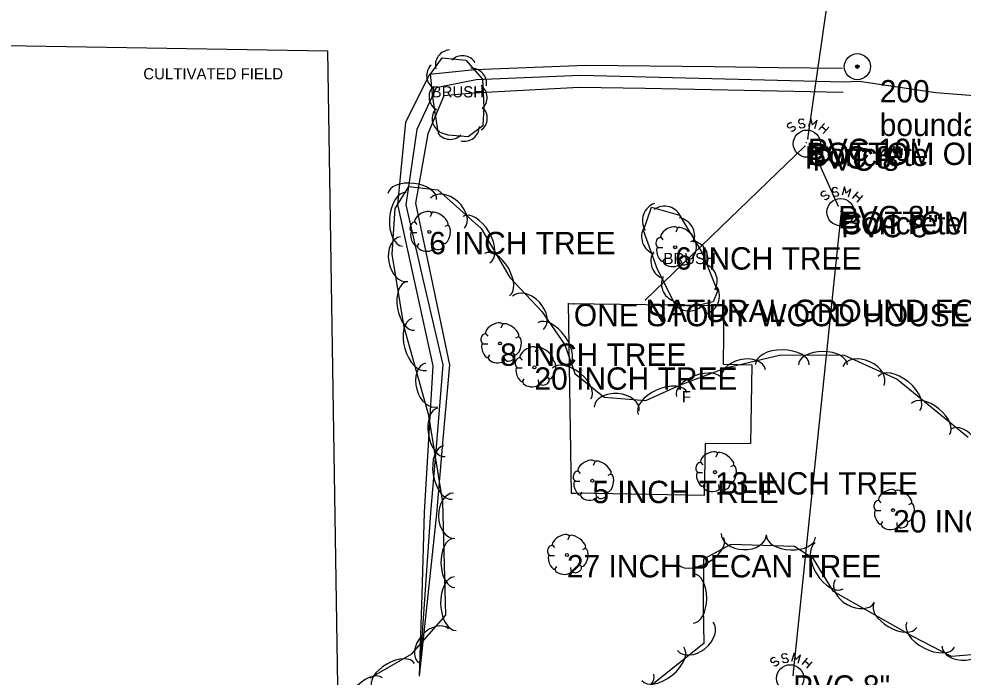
# Model space of a CAD drawing. Extents: x 1802180 to 1804859, y 572524 to 575172.
# Drawn here: x 1803144.4 to 1803355.3, y 573590.8 to 573738 of the extents above; entities that cross this region are included whole.
import ezdxf

# ---------------------------------------------------------------- set-up
doc = ezdxf.new("R2010")
doc.units = 0
for name, color, linetype in [('S_BUILDING', 7, 'Continuous'), ('S_BUILDING_ANNOT', 7, 'Continuous'), ('S_DITCHLINE', 7, 'Continuous'), ('S_IRON_PIN', 7, 'Continuous'), ('S_IRON_PIN_ANNOT', 7, 'Continuous'), ('S_MANHOLE_ANNOT', 7, 'Continuous'), ('S_MISC_BOUNDARY', 7, 'Continuous'), ('S_MISC_BOUNDARY_ANNOT', 7, 'Continuous'), ('S_MSC_PT_SYM', 7, 'Continuous'), ('S_SANITARY_SEWER', 7, 'Continuous'), ('S_SANITARY_SEWER_ANNOT', 7, 'Continuous'), ('S_SURVEY_TEXT_ANNOT', 7, 'Continuous'), ('S_TREE', 7, 'Continuous'), ('S_TREE_ANNOT', 7, 'Continuous'), ('S_UTL_PT_SYM', 7, 'Continuous')]:
    doc.layers.add(name, color=color, linetype=linetype)

msp = doc.modelspace()

# ---------------------------------------------------------------- linework, layer by layer
at = {"layer": 'S_BUILDING'}
for points in [[(1803267.07, 573674.42), (1803267.76, 573631.93), (1803268.74, 573631.95)], [(1803267.07, 573674.36), (1803301.86, 573673.93), (1803301.66, 573660.77), (1803308.1, 573660.63), (1803307.82, 573643.02), (1803297.64, 573642.97), (1803297.43, 573631.4), (1803268.85, 573631.96)]]:
    msp.add_lwpolyline(points, dxfattribs=at)
at = {"layer": 'S_DITCHLINE'}
for points in [[(1803328.37, 573726.88), (1803314.02, 573727.05), (1803299.67, 573727.21), (1803285.33, 573727.38), (1803270.98, 573727.54), (1803246.23, 573726.54), (1803236.12, 573725.56), (1803230.72, 573714.87), (1803228.93, 573696.45), (1803232.87, 573678.43), (1803236.81, 573660.4), (1803235.86, 573644.01), (1803234.91, 573627.61), (1803234.34, 573609.32), (1803233.78, 573591.03)], [(1803395.56, 573715.37), (1803382.79, 573717.59), (1803370.01, 573719.81), (1803349.16, 573721.42), (1803332.09, 573723.99), (1803328.45, 573723.83), (1803313.8, 573724.2), (1803299.14, 573724.57), (1803284.49, 573724.93), (1803269.83, 573725.3), (1803246.52, 573724.3), (1803237.61, 573722.54), (1803233.26, 573713.21), (1803230.79, 573696.36), (1803234.92, 573678.51), (1803239.04, 573660.67), (1803237.69, 573644.13), (1803236.34, 573627.59), (1803235.06, 573609.31), (1803233.78, 573591.03)], [(1803328.46, 573721.52), (1803313.73, 573721.81), (1803299, 573722.09), (1803284.28, 573722.37), (1803269.55, 573722.65), (1803245.87, 573721.33), (1803239.32, 573720.76), (1803235.74, 573712.29), (1803232.93, 573696.77), (1803236.73, 573678.71), (1803240.52, 573660.66), (1803239.1, 573643.99), (1803237.68, 573627.32), (1803235.73, 573609.17), (1803233.78, 573591.03)]]:
    msp.add_lwpolyline(points, dxfattribs=at)
at = {"layer": 'S_IRON_PIN'}
for radius in [2.91, 0.411, 0.262, 0.212, 0.145, 0.0822, 0.0581]:
    msp.add_circle((1803331.65, 573727.28), radius, dxfattribs=at)
at = {"layer": 'S_MISC_BOUNDARY'}
msp.add_lwpolyline([(1802880.88, 573735.6), (1803051.71, 573733.48), (1803213.27, 573730.83), (1803216.46, 573532.09), (1803301.63, 573530.07), (1803296.75, 573432.28), (1803274.96, 573355.36), (1803226.68, 573219.53), (1803202.19, 573137.5), (1803157.77, 572977.33), (1803158.5, 572726.69), (1802889.88, 572728.1)], dxfattribs=at)
at = {"layer": 'S_MSC_PT_SYM'}
msp.add_lwpolyline([(1803268.32, 573674.26), (1803268.32, 573674.31), (1803268.32, 573674.26), (1803268.27, 573674.26), (1803268.32, 573674.26), (1803268.32, 573674.21), (1803268.32, 573674.26), (1803268.37, 573674.26)], dxfattribs=at)
at = {"layer": 'S_SANITARY_SEWER'}
for p, q in [((1803320.59, 573711.18), (1803351.06, 573924.17)), ((1803316.07, 573714.37), (1803316, 573713.98)), ((1803316, 573713.98), (1803316.19, 573713.71)), ((1803316.62, 573714.76), (1803316.07, 573714.37)), ((1803316.19, 573713.71), (1803316.62, 573713.6)), ((1803317.04, 573714.68), (1803316.62, 573714.76)), ((1803316.62, 573713.6), (1803317.16, 573713.94)), ((1803317.16, 573713.94), (1803317.62, 573713.87)), ((1803317.62, 573713.87), (1803317.78, 573713.6)), ((1803317.78, 573713.6), (1803317.7, 573713.17)), ((1803323.05, 573713.13), (1803324.29, 573714.6)), ((1803323.71, 573713.91), (1803324.68, 573713.09)), ((1803325.26, 573713.79), (1803324.02, 573712.32)), ((1803317.16, 573712.78), (1803316.77, 573712.86)), ((1803317.7, 573713.17), (1803317.16, 573712.78)), ((1803319.94, 573709.5), (1803284.33, 573675.2)), ((1803327.34, 573696.17), (1803321.62, 573709.01)), ((1803323.59, 573699.08), (1803323.51, 573698.69)), ((1803323.51, 573698.69), (1803323.7, 573698.42)), ((1803324.13, 573699.47), (1803323.59, 573699.08)), ((1803324.55, 573699.39), (1803324.13, 573699.47)), ((1803324.13, 573698.31), (1803324.67, 573698.66)), ((1803324.67, 573698.66), (1803325.14, 573698.58)), ((1803325.14, 573698.58), (1803325.29, 573698.31)), ((1803330.56, 573697.84), (1803331.8, 573699.31)), ((1803331.22, 573698.62), (1803332.19, 573697.8)), ((1803323.7, 573698.42), (1803324.13, 573698.31)), ((1803324.67, 573697.49), (1803324.28, 573697.57)), ((1803325.21, 573697.88), (1803324.67, 573697.49)), ((1803325.29, 573698.31), (1803325.21, 573697.88)), ((1803332.77, 573698.5), (1803331.53, 573697.03)), ((1803317.29, 573591.23), (1803328.05, 573694.15)), ((1803312.88, 573595.25), (1803312.33, 573594.86)), ((1803313.3, 573595.17), (1803312.88, 573595.25)), ((1803312.33, 573594.86), (1803312.26, 573594.47)), ((1803312.26, 573594.47), (1803312.45, 573594.2)), ((1803312.45, 573594.2), (1803312.88, 573594.09)), ((1803312.88, 573594.09), (1803313.42, 573594.44)), ((1803313.42, 573593.27), (1803313.03, 573593.35)), ((1803313.42, 573594.44), (1803313.88, 573594.36)), ((1803313.96, 573593.66), (1803313.42, 573593.27)), ((1803313.88, 573594.36), (1803314.04, 573594.09)), ((1803314.04, 573594.09), (1803313.96, 573593.66)), ((1803319.31, 573593.62), (1803320.55, 573595.09)), ((1803319.97, 573594.4), (1803320.94, 573593.58)), ((1803321.52, 573594.28), (1803320.28, 573592.81))]:
    msp.add_line(p, q, dxfattribs=at)
for points in [[(1803319.72, 573715.3), (1803319.37, 573715.57), (1803318.71, 573715.49), (1803318.48, 573715.15), (1803318.52, 573714.84), (1803318.86, 573714.53), (1803319.48, 573714.64), (1803319.87, 573714.33), (1803319.91, 573714.02), (1803319.64, 573713.63), (1803319.02, 573713.56), (1803318.67, 573713.83)], [(1803322.16, 573713.44), (1803322.7, 573715.3), (1803321.65, 573714.29), (1803321.27, 573715.73), (1803320.72, 573713.87)], [(1803327.23, 573700.01), (1803326.88, 573700.28), (1803326.22, 573700.21), (1803325.99, 573699.86), (1803326.03, 573699.55), (1803326.38, 573699.24), (1803327, 573699.35), (1803327.38, 573699.04), (1803327.42, 573698.73), (1803327.15, 573698.35), (1803326.53, 573698.27), (1803326.18, 573698.54)], [(1803329.67, 573698.15), (1803330.21, 573700.01), (1803329.17, 573699), (1803328.78, 573700.44), (1803328.24, 573698.58)], [(1803315.98, 573595.79), (1803315.63, 573596.06), (1803314.97, 573595.99), (1803314.74, 573595.64), (1803314.78, 573595.33), (1803315.12, 573595.02), (1803315.74, 573595.13), (1803316.13, 573594.82), (1803316.17, 573594.51), (1803315.9, 573594.13), (1803315.28, 573594.05), (1803314.93, 573594.32)], [(1803318.42, 573593.93), (1803318.96, 573595.79), (1803317.91, 573594.78), (1803317.53, 573596.22), (1803316.98, 573594.36)]]:
    msp.add_lwpolyline(points, dxfattribs=at)
for centre in [(1803320.4, 573710.07), (1803327.91, 573694.78), (1803316.66, 573590.56)]:
    msp.add_circle(centre, 3.05, dxfattribs=at)
at = {"layer": 'S_TREE'}
for p, q in [((1803236.59, 573694.59), (1803236.2, 573693.74)), ((1803232.79, 573692.58), (1803233.29, 573692)), ((1803232.13, 573690.25), (1803233.26, 573690.25)), ((1803240.15, 573691.8), (1803239.49, 573691.53)), ((1803291.51, 573691.17), (1803291.13, 573690.32)), ((1803239.38, 573687.7), (1803238.91, 573688.12)), ((1803287.72, 573689.15), (1803288.22, 573688.57)), ((1803295.08, 573688.38), (1803294.42, 573688.11)), ((1803233.29, 573687.08), (1803233.76, 573687.77)), ((1803236.98, 573686.81), (1803236.9, 573687.58)), ((1803287.06, 573686.83), (1803288.18, 573686.83)), ((1803288.22, 573683.65), (1803288.68, 573684.35)), ((1803291.9, 573683.38), (1803291.82, 573684.15)), ((1803294.3, 573684.27), (1803293.84, 573684.7)), ((1803252.42, 573669.66), (1803252.03, 573668.81)), ((1803248.62, 573667.64), (1803249.13, 573667.06)), ((1803247.96, 573665.32), (1803249.09, 573665.32)), ((1803255.98, 573666.87), (1803255.33, 573666.6)), ((1803249.13, 573662.14), (1803249.59, 573662.84)), ((1803255.21, 573662.76), (1803254.74, 573663.19)), ((1803260.09, 573664.31), (1803259.7, 573663.46)), ((1803252.81, 573661.87), (1803252.73, 573662.65)), ((1803256.29, 573662.3), (1803256.8, 573661.71)), ((1803263.66, 573661.52), (1803263, 573661.25)), ((1803255.63, 573659.97), (1803256.76, 573659.97)), ((1803256.8, 573656.79), (1803257.26, 573657.49)), ((1803260.48, 573656.52), (1803260.4, 573657.3)), ((1803262.88, 573657.41), (1803262.42, 573657.84)), ((1803300.43, 573640.89), (1803300.04, 573640.03)), ((1803273.03, 573638.96), (1803272.64, 573638.11)), ((1803296.63, 573638.87), (1803297.13, 573638.29)), ((1803303.99, 573638.1), (1803303.33, 573637.83)), ((1803269.23, 573636.95), (1803269.74, 573636.36)), ((1803276.6, 573636.17), (1803275.94, 573635.9)), ((1803295.97, 573636.55), (1803297.09, 573636.55)), ((1803268.58, 573634.62), (1803269.7, 573634.62)), ((1803297.13, 573633.37), (1803297.6, 573634.07)), ((1803300.81, 573633.1), (1803300.74, 573633.87)), ((1803303.22, 573633.99), (1803302.75, 573634.42)), ((1803269.74, 573631.44), (1803270.2, 573632.14)), ((1803273.42, 573631.17), (1803273.34, 573631.95)), ((1803275.82, 573632.06), (1803275.36, 573632.49)), ((1803340.2, 573632.4), (1803339.81, 573631.55)), ((1803336.4, 573630.39), (1803336.9, 573629.81)), ((1803343.76, 573629.61), (1803343.1, 573629.34)), ((1803335.74, 573628.06), (1803336.86, 573628.06)), ((1803336.9, 573624.89), (1803337.37, 573625.58)), ((1803340.58, 573624.62), (1803340.51, 573625.39)), ((1803342.99, 573625.51), (1803342.52, 573625.93)), ((1803267.32, 573622.37), (1803266.94, 573621.52)), ((1803263.53, 573620.35), (1803264.03, 573619.77)), ((1803270.89, 573619.58), (1803270.23, 573619.31)), ((1803262.87, 573618.03), (1803263.99, 573618.03)), ((1803264.03, 573614.85), (1803264.49, 573615.55)), ((1803267.71, 573614.58), (1803267.63, 573615.35)), ((1803270.11, 573615.47), (1803269.65, 573615.9))]:
    msp.add_line(p, q, dxfattribs=at)
for points in [[(1803238, 573712.73), (1803236.8, 573720.47), (1803236.3, 573725.64), (1803238.93, 573729.25), (1803244.17, 573728.74), (1803247.93, 573724.47), (1803248.23, 573718.22), (1803247.98, 573714.07), (1803244.73, 573711.61), (1803240.24, 573711.99), (1803238, 573712.73)], [(1803222.81, 573590.7), (1803232.15, 573596.04), (1803239.77, 573604.7), (1803239.03, 573629.95), (1803235.95, 573649.28), (1803230.42, 573669.08), (1803227.75, 573685.36), (1803228.45, 573695.61), (1803231.48, 573700.52), (1803237.93, 573699.73)], [(1803237.93, 573699.73), (1803247.62, 573691.09), (1803254.06, 573680.13), (1803261.15, 573672.56), (1803266.28, 573665.12), (1803268.56, 573658.68), (1803275.1, 573653.42), (1803284.4, 573652.66), (1803292.13, 573656.16), (1803302.29, 573659.94), (1803314.56, 573662.86), (1803328.68, 573662.79), (1803340.52, 573657.42), (1803356.41, 573644.47)], [(1803290.74, 573674.59), (1803287.03, 573681.92), (1803283.86, 573690.67), (1803285.67, 573695.91), (1803291.93, 573694.11), (1803297, 573685.64), (1803300.38, 573677.09), (1803299.44, 573674.71), (1803295.16, 573673.66), (1803292.71, 573673.92), (1803290.74, 573674.59)], [(1803359.91, 573596.02), (1803352.65, 573595.44), (1803344.01, 573599.94), (1803326.3, 573609.96), (1803321.85, 573617.27), (1803317.63, 573620.04), (1803303.37, 573620.44), (1803297.28, 573617.22), (1803297.2, 573606.49), (1803297.38, 573598.34), (1803285.61, 573588.98)]]:
    msp.add_lwpolyline(points, dxfattribs=at)
for centre in [(1803236.03, 573690.35), (1803290.96, 573686.92), (1803251.86, 573665.41), (1803259.53, 573660.07), (1803299.87, 573636.64), (1803272.47, 573634.72), (1803339.64, 573628.16), (1803266.77, 573618.12)]:
    msp.add_circle(centre, 0.341, dxfattribs=at)
for centre, radius, start, end in [((1803240.76, 573727.66), 3.36, 93.1463, 194.7432), ((1803243.48, 573726.37), 3.36, 33.5622, 135.1591), ((1803238.8, 573725.25), 3.36, 134.7561, 236.353), ((1803245.47, 573723.55), 3.36, 350.6152, 92.2121), ((1803239.34, 573720.55), 3.36, 137.9753, 239.5722), ((1803245.61, 573720.37), 3.36, 311.9833, 53.5802), ((1803240.03, 573715.68), 3.36, 137.9753, 239.5722), ((1803245.63, 573715.78), 3.36, 305.742, 47.3389), ((1803243.87, 573713.99), 3.36, 256.3636, 357.9605), ((1803240.69, 573714.39), 3.36, 214.2993, 315.8962), ((1803287.72, 573692.89), 4.06, 110.1705, 211.7674), ((1803288.58, 573692.03), 4.06, 23.1379, 124.7348), ((1803291.26, 573689.46), 4.06, 340.1192, 81.7161), ((1803287.51, 573689.28), 4.06, 149.1194, 250.7163), ((1803294.24, 573684.32), 4.06, 340.1192, 81.7161), ((1803289.59, 573683.78), 4.06, 149.1194, 250.7163), ((1803296.3, 573679.35), 4.06, 330.7442, 72.3411), ((1803291.96, 573678.74), 4.06, 156.0587, 257.6557), ((1803296.81, 573676.01), 4.06, 287.6923, 29.2892), ((1803294.07, 573676.72), 4.06, 213.1535, 314.7504)]:
    msp.add_arc(centre, radius, start, end, dxfattribs=at)
for centre, major_axis, ratio, start_param, end_param in [((1803232.24, 573698.24), (-5.44, 0.66), 0.540699, 3.141593, 6.283185), ((1803230.46, 573693.17), (-0.41, -6), 0.55008, 3.141593, 6.283185), ((1803240.1, 573694.53), (-3.79, 3.38), 0.685311, 3.141593, 6.283185), ((1803234.69, 573693.55), (1.86, 1.08), 0.471018, 0, 3.141593), ((1803238.35, 573693.23), (-1.81, 1.36), 0.405113, 3.141593, 6.283186), ((1803246.55, 573688.63), (-3.04, 5.18), 0.55008, 3.141593, 6.283185), ((1803232.46, 573691.44), (0.31, 1.03), 0.646762, 0, 3.141593), ((1803232.76, 573688.79), (-0.61, 1.6), 0.420543, 6.283185, 9.424777), ((1803239.7, 573689.82), (0.46, 2.04), 0.482994, 3.141593, 6.283185), ((1803289.62, 573690.12), (1.86, 1.08), 0.471018, 0, 3.141593), ((1803293.27, 573689.8), (-1.81, 1.36), 0.405113, 3.141593, 6.283186), ((1803230.41, 573684.27), (0.82, -5.01), 0.685311, 3.141593, 6.283185), ((1803287.38, 573688.01), (0.31, 1.03), 0.646762, 0, 3.141593), ((1803294.63, 573686.39), (0.46, 2.04), 0.482994, 3.141593, 6.283185), ((1803235.23, 573687.01), (-1.83, 0.19), 0.529943, 0, 3.141593), ((1803238.18, 573687.3), (1.09, 0.46), 0.711534, 3.141592, 6.283185), ((1803251.15, 573680.79), (-2.77, 4.72), 0.540699, 3.141593, 6.283185), ((1803287.69, 573685.36), (-0.61, 1.6), 0.420543, 6.283185, 9.424777), ((1803290.15, 573683.58), (-1.83, 0.19), 0.529943, 0, 3.141593), ((1803293.11, 573683.87), (1.09, 0.46), 0.711534, 3.141592, 6.283185), ((1803231.85, 573673.81), (0.88, -5.41), 0.540699, 3.141593, 6.283185), ((1803258.1, 573672.25), (-3.47, 3.7), 0.685311, 3.141593, 6.283185), ((1803233.76, 573665.19), (1.62, -5.79), 0.55008, 3.141593, 6.283185), ((1803250.52, 573668.62), (1.86, 1.08), 0.471018, 0, 3.141593), ((1803254.18, 573668.29), (-1.81, 1.36), 0.405113, 3.141593, 6.283186), ((1803263.69, 573665.06), (-3.41, 4.95), 0.55008, 3.141593, 6.283185), ((1803248.29, 573666.5), (0.31, 1.03), 0.646762, 0, 3.141593), ((1803255.53, 573664.88), (0.46, 2.04), 0.482994, 3.141593, 6.283185), ((1803248.6, 573663.85), (-0.61, 1.6), 0.420543, 6.283185, 9.424777), ((1803258.2, 573663.27), (1.86, 1.08), 0.471018, 0, 3.141593), ((1803254.01, 573662.36), (1.09, 0.46), 0.711534, 3.141592, 6.283185), ((1803261.85, 573662.94), (-1.81, 1.36), 0.405113, 3.141593, 6.283186), ((1803314.89, 573660.68), (-6.01, 0.03), 0.55008, 3.141593, 6.283185), ((1803323.97, 573660.64), (-5.48, 0.02), 0.540699, 3.141593, 6.283185), ((1803236.57, 573656.12), (1.37, -4.89), 0.685311, 3.141593, 6.283185), ((1803251.06, 573662.07), (-1.83, 0.19), 0.529943, 0, 3.141593), ((1803255.96, 573661.15), (0.31, 1.03), 0.646762, 0, 3.141593), ((1803263.21, 573659.54), (0.46, 2.04), 0.482994, 3.141593, 6.283185), ((1803267.85, 573656.46), (-4.27, 3.43), 0.540699, 3.141593, 6.283185), ((1803306.22, 573658.37), (-4.94, -1.17), 0.685311, 3.141593, 6.283185), ((1803333.01, 573658.15), (-4.62, 2.1), 0.685311, 3.141593, 6.283185), ((1803256.27, 573658.5), (-0.61, 1.6), 0.420543, 6.283185, 9.424777), ((1803296.4, 573655.43), (-5.13, -1.91), 0.540699, 3.141593, 6.283185), ((1803340.96, 573654.26), (-4.66, 3.8), 0.55008, 3.141593, 6.283185), ((1803258.73, 573656.72), (-1.83, 0.19), 0.529943, 0, 3.141593), ((1803261.69, 573657.01), (1.09, 0.46), 0.711534, 3.141592, 6.283185), ((1803288.17, 573651.98), (-5.48, -2.48), 0.55008, 3.141593, 6.283185), ((1803277.89, 573650.74), (-5.06, 0.42), 0.685311, 3.141593, 6.283185), ((1803348, 573648.52), (-4.24, 3.46), 0.540699, 3.141593, 6.283185), ((1803238.75, 573645.54), (0.86, -5.41), 0.540699, 3.141593, 6.283185), ((1803355.12, 573641.92), (-2.69, 4.3), 0.685311, 3.141593, 6.283185), ((1803240.18, 573636.57), (0.95, -5.94), 0.55008, 3.141593, 6.283185), ((1803271.14, 573637.92), (1.86, 1.08), 0.471018, 0, 3.141593), ((1803298.53, 573639.84), (1.86, 1.08), 0.471018, 0, 3.141593), ((1803302.19, 573639.52), (-1.81, 1.36), 0.405113, 3.141593, 6.283186), ((1803274.79, 573637.59), (-1.81, 1.36), 0.405113, 3.141593, 6.283186), ((1803296.3, 573637.73), (0.31, 1.03), 0.646762, 0, 3.141593), ((1803303.54, 573636.11), (0.46, 2.04), 0.482994, 3.141593, 6.283185), ((1803268.9, 573635.8), (0.31, 1.03), 0.646762, 0, 3.141593), ((1803276.15, 573634.19), (0.46, 2.04), 0.482994, 3.141593, 6.283185), ((1803296.6, 573635.08), (-0.61, 1.6), 0.420543, 6.283185, 9.424777), ((1803269.21, 573633.15), (-0.61, 1.6), 0.420543, 6.283185, 9.424777), ((1803299.06, 573633.3), (-1.83, 0.19), 0.529943, 0, 3.141593), ((1803302.02, 573633.59), (1.09, 0.46), 0.711534, 3.141592, 6.283185), ((1803241.57, 573626.9), (0.15, -5.07), 0.685311, 3.141593, 6.283185), ((1803271.67, 573631.37), (-1.83, 0.19), 0.529943, 0, 3.141593), ((1803274.63, 573631.66), (1.09, 0.46), 0.711534, 3.141592, 6.283185), ((1803338.3, 573631.36), (1.86, 1.08), 0.471018, 0, 3.141593), ((1803341.96, 573631.04), (-1.81, 1.36), 0.405113, 3.141593, 6.283186), ((1803336.07, 573629.25), (0.31, 1.03), 0.646762, 0, 3.141593), ((1803343.31, 573627.63), (0.46, 2.04), 0.482994, 3.141593, 6.283185), ((1803336.37, 573626.6), (-0.61, 1.6), 0.420543, 6.283185, 9.424777), ((1803338.83, 573624.82), (-1.83, 0.19), 0.529943, 0, 3.141593), ((1803341.79, 573625.11), (1.09, 0.46), 0.711534, 3.141592, 6.283185), ((1803265.43, 573621.32), (1.86, 1.08), 0.471018, 0, 3.141593), ((1803269.08, 573621), (-1.81, 1.36), 0.405113, 3.141593, 6.283186), ((1803306.29, 573622.8), (5.07, -0.14), 0.685311, 3.141593, 6.283185), ((1803241.61, 573616.34), (0.16, -5.47), 0.540699, 3.141593, 6.283185), ((1803296.49, 573619.26), (5.31, 2.81), 0.55008, 3.141593, 6.283185), ((1803316.84, 573622.23), (5.47, -0.15), 0.540699, 3.141593, 6.283185), ((1803325.36, 573615.69), (3.13, -5.14), 0.55008, 3.141593, 6.283185), ((1803263.19, 573619.21), (0.31, 1.03), 0.646762, 0, 3.141593), ((1803270.44, 573617.59), (0.46, 2.04), 0.482994, 3.141593, 6.283185), ((1803263.5, 573616.56), (-0.61, 1.6), 0.420543, 6.283185, 9.424777), ((1803265.96, 573614.78), (-1.83, 0.19), 0.529943, 0, 3.141593), ((1803268.92, 573615.07), (1.09, 0.46), 0.711534, 3.141592, 6.283185), ((1803241.87, 573607.26), (0.18, -6.01), 0.55008, 3.141593, 6.283185), ((1803295.04, 573608.41), (0.04, 5.48), 0.540699, 3.141593, 6.283185), ((1803331.08, 573610.06), (4.42, -2.5), 0.685311, 3.141593, 6.283185), ((1803340.14, 573604.63), (4.77, -2.7), 0.540699, 3.141593, 6.283185), ((1803236.98, 573597.84), (-3.36, -3.81), 0.685311, 3.141593, 6.283185), ((1803295.46, 573599.94), (3.97, 3.16), 0.685311, 3.141593, 6.283185), ((1803348.03, 573600.29), (5.33, -2.78), 0.55008, 3.141593, 6.283185), ((1803288.2, 573593.82), (4.7, 3.74), 0.55008, 3.141593, 6.283185), ((1803355.59, 573598.12), (5.06, 0.4), 0.685311, 3.141593, 6.283185), ((1803228.01, 573591.17), (-4.75, -2.72), 0.540699, 3.141593, 6.283185), ((1803221.76, 573585.97), (-3.79, -4.67), 0.55008, 3.141593, 6.283185), ((1803281.06, 573589.53), (5.1, 2), 0.540699, 3.141593, 6.283185)]:
    msp.add_ellipse(centre, major_axis=major_axis, ratio=ratio, start_param=start_param, end_param=end_param, dxfattribs=at)
at = {"layer": 'S_UTL_PT_SYM'}
for points in [[(1803320.59, 573711.18), (1803320.59, 573711.23), (1803320.59, 573711.18), (1803320.54, 573711.18), (1803320.59, 573711.18), (1803320.59, 573711.13), (1803320.59, 573711.18), (1803320.64, 573711.18)], [(1803319.94, 573709.5), (1803319.94, 573709.55), (1803319.94, 573709.5), (1803319.89, 573709.5), (1803319.94, 573709.5), (1803319.94, 573709.45), (1803319.94, 573709.5), (1803319.99, 573709.5)], [(1803320.25, 573710.3), (1803320.25, 573710.35), (1803320.25, 573710.3), (1803320.2, 573710.3), (1803320.25, 573710.3), (1803320.25, 573710.25), (1803320.25, 573710.3), (1803320.3, 573710.3)], [(1803321.62, 573709.01), (1803321.62, 573709.06), (1803321.62, 573709.01), (1803321.57, 573709.01), (1803321.62, 573709.01), (1803321.62, 573708.96), (1803321.62, 573709.01), (1803321.67, 573709.01)], [(1803327.34, 573696.17), (1803327.34, 573696.22), (1803327.34, 573696.17), (1803327.29, 573696.17), (1803327.34, 573696.17), (1803327.34, 573696.12), (1803327.34, 573696.17), (1803327.39, 573696.17)], [(1803327.98, 573694.9), (1803327.98, 573694.95), (1803327.98, 573694.9), (1803327.93, 573694.9), (1803327.98, 573694.9), (1803327.98, 573694.85), (1803327.98, 573694.9), (1803328.03, 573694.9)], [(1803328.05, 573694.15), (1803328.05, 573694.2), (1803328.05, 573694.15), (1803328, 573694.15), (1803328.05, 573694.15), (1803328.05, 573694.1), (1803328.05, 573694.15), (1803328.1, 573694.15)], [(1803284.33, 573675.2), (1803284.33, 573675.25), (1803284.33, 573675.2), (1803284.28, 573675.2), (1803284.33, 573675.2), (1803284.33, 573675.15), (1803284.33, 573675.2), (1803284.38, 573675.2)], [(1803317.29, 573591.23), (1803317.29, 573591.28), (1803317.29, 573591.23), (1803317.24, 573591.23), (1803317.29, 573591.23), (1803317.29, 573591.18), (1803317.29, 573591.23), (1803317.34, 573591.23)]]:
    msp.add_lwpolyline(points, dxfattribs=at)

# ---------------------------------------------------------------- texts
at = {"layer": 'S_BUILDING_ANNOT'}
msp.add_text('F', height=2.5, dxfattribs=at).set_placement((1803292.47, 573652.25))
at = {"layer": 'S_IRON_PIN_ANNOT'}
for s, p in [('200', (1803336.65, 573719.28)), ('boundary monument ', (1803336.65, 573711.78))]:
    msp.add_text(s, height=5, dxfattribs=at).set_placement(p)
at = {"layer": 'S_MANHOLE_ANNOT'}
for p in [(1803320.25, 573705.3), (1803327.98, 573689.9)]:
    msp.add_text('BOTTOM OF MANHOLE', height=5, dxfattribs=at).set_placement(p)
at = {"layer": 'S_MISC_BOUNDARY_ANNOT'}
msp.add_text('CULTIVATED FIELD', height=2.5, dxfattribs=at).set_placement((1803172.16, 573724.44))
at = {"layer": 'S_SANITARY_SEWER_ANNOT'}
for s, p in [('PVC 10" ', (1803320.59, 573706.18)), ('PVC 6" ', (1803319.94, 573704.5)), ('Concrete', (1803320.4, 573705.07)), ('PVC 8"', (1803321.62, 573704.01)), ('PVC 8" ', (1803327.34, 573691.17)), ('Concrete', (1803327.91, 573689.78)), ('PVC 8" ', (1803328.05, 573689.15)), ('NATURAL GROUND FOR DIRECTION ON ', (1803284.33, 573670.2)), ('PVC 8"', (1803317.29, 573586.23))]:
    msp.add_text(s, height=5, dxfattribs=at).set_placement(p)
at = {"layer": 'S_SURVEY_TEXT_ANNOT'}
msp.add_text('ONE STORY WOOD HOUSE VINYL SIDI', height=5, dxfattribs=at).set_placement((1803268.32, 573669.26))
at = {"layer": 'S_TREE_ANNOT'}
for s, height, p in [('BRUSH', 2.5, (1803236.56, 573720.41)), ('6 INCH TREE', 5, (1803236.03, 573685.35)), ('6 INCH TREE', 5, (1803290.96, 573681.92)), ('BRUSH', 2.5, (1803288.35, 573683.15)), ('8 INCH TREE', 5, (1803251.86, 573660.41)), ('20 INCH TREE', 5, (1803259.53, 573655.07)), ('13 INCH TREE', 5, (1803299.87, 573631.64)), ('5 INCH TREE', 5, (1803272.47, 573629.72)), ('20 INCH SPLIT PECANTREE', 5, (1803339.64, 573623.16)), ('27 INCH PECAN TREE', 5, (1803266.77, 573613.12))]:
    msp.add_text(s, height=height, dxfattribs=at).set_placement(p)

doc.saveas('drawing.dxf')
